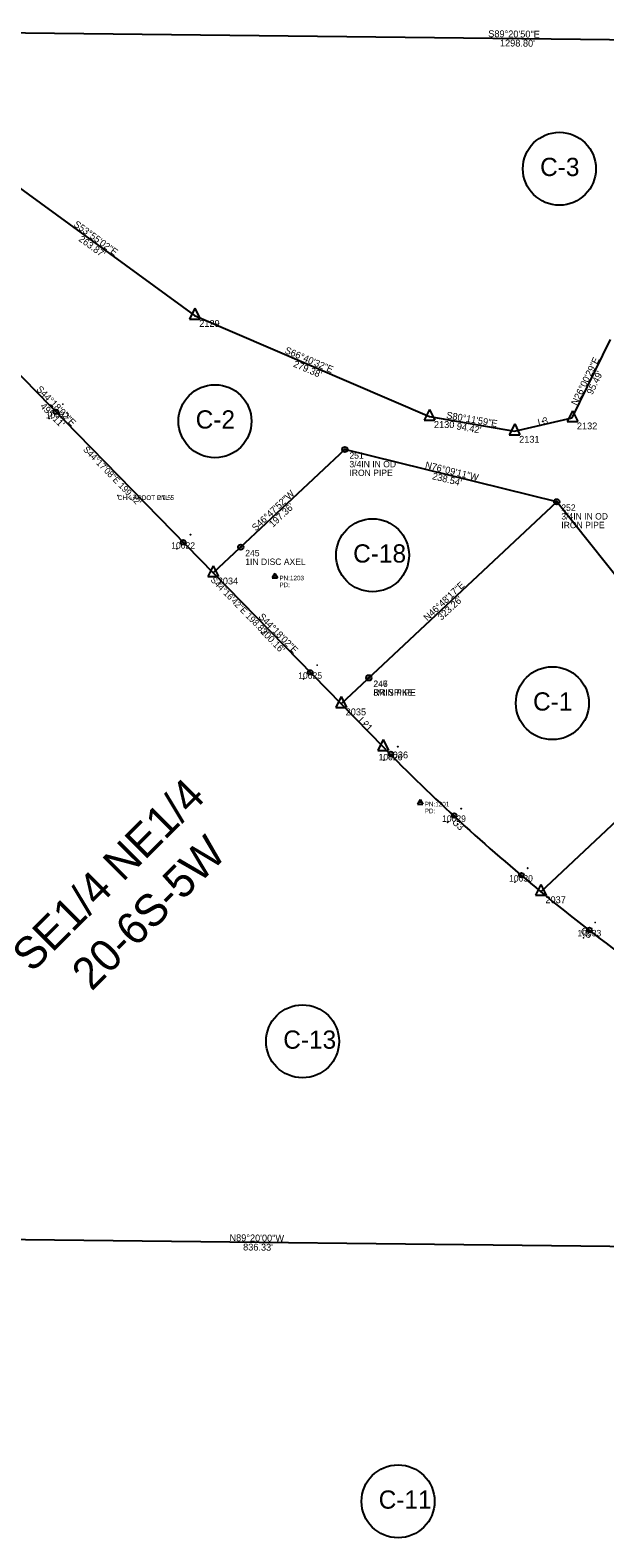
# Model space of a CAD drawing. Extents: x 1431802 to 1457777, y 1852108 to 1876350.
# Drawn here: x 1442574 to 1443202, y 1854628 to 1856278 of the extents above; entities that cross this region are included whole.
import ezdxf

# ---------------------------------------------------------------- set-up
doc = ezdxf.new("R2010")
doc.units = 0
for name, color, linetype in [('Default', 7, 'Continuous'), ('S_CAL_CORNER', 7, 'Continuous'), ('S_CAL_CORNER_ANNOT', 7, 'Continuous'), ('S_EXISTING_ALIGNMENT', 7, 'Continuous'), ('S_EXISTING_ALIGNMENT_ANNOT', 7, 'Continuous'), ('S_IRON_PIN', 7, 'Continuous'), ('S_IRON_PIN_ANNOT', 7, 'Continuous'), ('S_MSC_PT_SYM', 7, 'Continuous'), ('S_PROPERTY', 7, 'Continuous'), ('S_PROPERTY_ANNOT', 7, 'Continuous'), ('S_RDW_PT_SYM', 7, 'Continuous'), ('S_SECONDARY_CTL', 7, 'Continuous'), ('S_SECONDARY_CTL_ANNOT', 7, 'Continuous'), ('S_SECTION_TEXT', 7, 'Continuous'), ('S_SIXTEEN_SECTION', 7, 'Continuous'), ('S_SIXTEEN_SECTION_ANNOT', 7, 'Continuous'), ('S_SURVEY_TEXT_ANNOT', 7, 'Continuous')]:
    doc.layers.add(name, color=color, linetype=linetype)

msp = doc.modelspace()

# ---------------------------------------------------------------- linework, layer by layer
at = {"layer": 'Default'}
for points in [[(1443134.5, 1855849.7), (1443134.5, 1855849.8), (1443134.5, 1855849.7), (1443134.5, 1855849.7), (1443134.5, 1855849.7), (1443134.5, 1855849.7), (1443134.5, 1855849.7), (1443134.6, 1855849.7)], [(1442939.8, 1855519.7), (1442939.9, 1855519.7), (1442939.8, 1855519.7), (1442939.8, 1855519.7), (1442939.8, 1855519.7), (1442939.8, 1855519.6), (1442939.8, 1855519.7), (1442939.9, 1855519.6)], [(1443041.6, 1855409.2), (1443041.7, 1855409.2), (1443041.6, 1855409.2), (1443041.6, 1855409.2), (1443041.6, 1855409.2), (1443041.6, 1855409.2), (1443041.6, 1855409.2), (1443041.7, 1855409.2)], [(1443181.9, 1855290.9), (1443182, 1855290.9), (1443181.9, 1855290.9), (1443181.9, 1855290.9), (1443181.9, 1855290.9), (1443181.9, 1855290.8), (1443181.9, 1855290.9), (1443182, 1855290.8)]]:
    msp.add_lwpolyline(points, dxfattribs=at)
at = {"layer": 'S_CAL_CORNER'}
for p, q in [((1442754.3, 1855973.5), (1442748.4, 1855961.6)), ((1442748.4, 1855961.6), (1442760.1, 1855961.6)), ((1442754.3, 1855973.5), (1442760.1, 1855961.6)), ((1443010.8, 1855862.8), (1443004.9, 1855851)), ((1443010.8, 1855862.8), (1443016.6, 1855851)), ((1443004.9, 1855851), (1443016.6, 1855851)), ((1443103.9, 1855846.8), (1443098, 1855835)), ((1443103.9, 1855846.8), (1443109.7, 1855835)), ((1443167, 1855861.3), (1443161.2, 1855849.5)), ((1443161.2, 1855849.5), (1443172.9, 1855849.5)), ((1443167, 1855861.3), (1443172.9, 1855849.5)), ((1443098, 1855835), (1443109.7, 1855835)), ((1442774.5, 1855691.8), (1442768.6, 1855680)), ((1442774.5, 1855691.8), (1442780.3, 1855680)), ((1442768.6, 1855680), (1442780.3, 1855680)), ((1442914.3, 1855548.6), (1442908.4, 1855536.7)), ((1442908.4, 1855536.7), (1442920.1, 1855536.7)), ((1442914.3, 1855548.6), (1442920.1, 1855536.7)), ((1442960.2, 1855501.5), (1442954.3, 1855489.7)), ((1442960.2, 1855501.5), (1442966, 1855489.7)), ((1442954.3, 1855489.7), (1442966, 1855489.7)), ((1443132.6, 1855343.1), (1443126.7, 1855331.3)), ((1443132.6, 1855343.1), (1443138.4, 1855331.3)), ((1443126.7, 1855331.3), (1443138.4, 1855331.3))]:
    msp.add_line(p, q, dxfattribs=at)
at = {"layer": 'S_EXISTING_ALIGNMENT'}
for centre in [(1442602.6, 1855860.1), (1442741.7, 1855717.4), (1442880.5, 1855575.1), (1442968.6, 1855485.9), (1443037.8, 1855418.6), (1443111.3, 1855353.3), (1443185.6, 1855293.4)]:
    msp.add_circle(centre, 2.5, dxfattribs=at)
at = {"layer": 'S_IRON_PIN'}
for centre, radius in [((1442918.3, 1855818.9), 2.91), ((1442918.3, 1855818.9), 0.411), ((1442918.3, 1855818.9), 0.262), ((1442918.3, 1855818.9), 0.212), ((1442918.3, 1855818.9), 0.145), ((1442918.3, 1855818.9), 0.0581), ((1442918.3, 1855818.9), 0.0822), ((1443149.9, 1855761.8), 2.91), ((1443149.9, 1855761.8), 0.411), ((1443149.9, 1855761.8), 0.262), ((1443149.9, 1855761.8), 0.212), ((1443149.9, 1855761.8), 0.145), ((1443149.9, 1855761.8), 0.0581), ((1443149.9, 1855761.8), 0.0822), ((1442804.5, 1855712.1), 2.91), ((1442804.5, 1855712.1), 0.411), ((1442804.5, 1855712.1), 0.212), ((1442804.5, 1855712.1), 0.262), ((1442804.5, 1855712.1), 0.145), ((1442804.5, 1855712.1), 0.0581), ((1442804.5, 1855712.1), 0.0822), ((1442944.5, 1855569.2), 2.91), ((1442944.5, 1855569), 2.91), ((1442944.5, 1855569.2), 0.411), ((1442944.5, 1855569), 0.411), ((1442944.5, 1855569.2), 0.212), ((1442944.5, 1855569.2), 0.262), ((1442944.5, 1855569), 0.212), ((1442944.5, 1855569), 0.262), ((1442944.5, 1855569.2), 0.145), ((1442944.5, 1855569), 0.145), ((1442944.5, 1855569), 0.0822), ((1442944.5, 1855569.2), 0.0822), ((1442944.5, 1855569.2), 0.0581), ((1442944.5, 1855569), 0.0581)]:
    msp.add_circle(centre, radius, dxfattribs=at)
at = {"layer": 'S_MSC_PT_SYM'}
for points in [[(1442670.3, 1855768.6), (1442670.3, 1855768.7), (1442670.3, 1855768.6), (1442670.3, 1855768.6), (1442670.3, 1855768.6), (1442670.3, 1855768.6), (1442670.3, 1855768.6), (1442670.4, 1855768.6)], [(1442670.3, 1855768.6), (1442670.3, 1855768.7), (1442670.3, 1855768.6), (1442670.3, 1855768.6), (1442670.3, 1855768.6), (1442670.3, 1855768.6), (1442670.3, 1855768.6), (1442670.4, 1855768.6)], [(1442670.3, 1855768.7), (1442670.3, 1855768.7), (1442670.3, 1855768.7), (1442670.3, 1855768.7), (1442670.3, 1855768.7), (1442670.3, 1855768.6), (1442670.3, 1855768.7), (1442670.4, 1855768.7)]]:
    msp.add_lwpolyline(points, dxfattribs=at)
at = {"layer": 'S_PROPERTY'}
for p, q in [((1442540.9, 1856120.9), (1442754.2, 1855965.5)), ((1442428.6, 1856038.2), (1442774.4, 1855683.8)), ((1442754.2, 1855965.5), (1443010.7, 1855854.9)), ((1443166.9, 1855853.4), (1443208.8, 1855939.2)), ((1443010.7, 1855854.9), (1443103.8, 1855838.8)), ((1443103.8, 1855838.8), (1443166.9, 1855853.4)), ((1442918.3, 1855818.9), (1442774.4, 1855683.8)), ((1443149.9, 1855761.8), (1442918.3, 1855818.9)), ((1442914.2, 1855540.6), (1443149.9, 1855761.8)), ((1443336.5, 1855526.9), (1443149.9, 1855761.8)), ((1442774.4, 1855683.8), (1442914.2, 1855540.6)), ((1442914.2, 1855540.6), (1442960.1, 1855493.5)), ((1443132.5, 1855335.1), (1443336.5, 1855526.9)), ((1443244.7, 1854946.5), (1442408.5, 1854956.2))]:
    msp.add_line(p, q, dxfattribs=at)
for centre in [(1443152.8, 1856126), (1442776.4, 1855849.8), (1442948.6, 1855703.2), (1443145.1, 1855541.4), (1442872.1, 1855171.5), (1442976.5, 1854668.3)]:
    msp.add_circle(centre, 39.9, dxfattribs=at)
for start, end in [(224.3006, 230.5345), (230.5345, 234.0557)]:
    msp.add_arc((1444501, 1856997.2), 2153, start, end, dxfattribs=at)
at = {"layer": 'S_RDW_PT_SYM'}
for points in [[(1442610, 1855868.3), (1442610, 1855868.4), (1442610, 1855868.3), (1442610, 1855868.3), (1442610, 1855868.3), (1442610, 1855868.3), (1442610, 1855868.3), (1442610.1, 1855868.3)], [(1442595.2, 1855852.9), (1442595.2, 1855853), (1442595.2, 1855852.9), (1442595.1, 1855852.9), (1442595.2, 1855852.9), (1442595.2, 1855852.9), (1442595.2, 1855852.9), (1442595.2, 1855852.9)], [(1442749.7, 1855725.8), (1442749.7, 1855725.8), (1442749.7, 1855725.8), (1442749.6, 1855725.8), (1442749.7, 1855725.8), (1442749.7, 1855725.7), (1442749.7, 1855725.8), (1442749.7, 1855725.8)], [(1442734.7, 1855710.4), (1442734.7, 1855710.4), (1442734.7, 1855710.4), (1442734.7, 1855710.4), (1442734.7, 1855710.4), (1442734.7, 1855710.3), (1442734.7, 1855710.4), (1442734.8, 1855710.4)], [(1442888.1, 1855582.9), (1442888.1, 1855583), (1442888.1, 1855582.9), (1442888, 1855582.9), (1442888.1, 1855582.9), (1442888.1, 1855582.9), (1442888.1, 1855582.9), (1442888.1, 1855582.9)], [(1442873.3, 1855568.1), (1442873.3, 1855568.2), (1442873.3, 1855568.1), (1442873.3, 1855568.1), (1442873.3, 1855568.1), (1442873.3, 1855568), (1442873.3, 1855568.1), (1442873.4, 1855568.1)], [(1442976.2, 1855493.8), (1442976.2, 1855493.9), (1442976.2, 1855493.8), (1442976.1, 1855493.8), (1442976.2, 1855493.8), (1442976.2, 1855493.8), (1442976.2, 1855493.8), (1442976.2, 1855493.8)], [(1442960.9, 1855479.1), (1442960.9, 1855479.2), (1442960.9, 1855479.1), (1442960.8, 1855479.1), (1442960.9, 1855479.1), (1442960.9, 1855479.1), (1442960.9, 1855479.1), (1442960.9, 1855479.1)], [(1443045.5, 1855426), (1443045.5, 1855426.1), (1443045.5, 1855426), (1443045.5, 1855426), (1443045.5, 1855426), (1443045.5, 1855426), (1443045.5, 1855426), (1443045.6, 1855426)], [(1443030.7, 1855411.2), (1443030.7, 1855411.3), (1443030.7, 1855411.2), (1443030.6, 1855411.2), (1443030.7, 1855411.2), (1443030.7, 1855411.2), (1443030.7, 1855411.2), (1443030.7, 1855411.2)], [(1443118.2, 1855361.1), (1443118.2, 1855361.1), (1443118.2, 1855361.1), (1443118.1, 1855361.1), (1443118.2, 1855361.1), (1443118.2, 1855361), (1443118.2, 1855361.1), (1443118.2, 1855361.1)], [(1443104, 1855345.5), (1443104, 1855345.6), (1443104, 1855345.5), (1443103.9, 1855345.5), (1443104, 1855345.5), (1443104, 1855345.5), (1443104, 1855345.5), (1443104, 1855345.5)], [(1443192, 1855301.4), (1443192, 1855301.5), (1443192, 1855301.4), (1443191.9, 1855301.4), (1443192, 1855301.4), (1443192, 1855301.4), (1443192, 1855301.4), (1443192, 1855301.4)], [(1443179, 1855284.7), (1443179, 1855284.8), (1443179, 1855284.7), (1443179, 1855284.7), (1443179, 1855284.7), (1443179, 1855284.7), (1443179, 1855284.7), (1443179.1, 1855284.7)]]:
    msp.add_lwpolyline(points, dxfattribs=at)
at = {"layer": 'S_SECONDARY_CTL'}
for p, q in [((1442841.8, 1855683.4), (1442838.8, 1855678.4)), ((1442841.8, 1855683.4), (1442844.7, 1855678.4)), ((1442838.8, 1855678.4), (1442844.7, 1855678.4)), ((1443000.6, 1855436.1), (1442997.6, 1855431.1)), ((1443000.6, 1855436.1), (1443003.5, 1855431.1)), ((1442997.6, 1855431.1), (1443003.5, 1855431.1))]:
    msp.add_line(p, q, dxfattribs=at)
for centre, radius in [((1442841.8, 1855680.8), 0.311), ((1442841.8, 1855680.8), 0.183), ((1442841.8, 1855680.8), 0.103), ((1443000.6, 1855433.5), 0.311), ((1443000.6, 1855433.5), 0.183), ((1443000.6, 1855433.5), 0.103)]:
    msp.add_circle(centre, radius, dxfattribs=at)
at = {"layer": 'S_SIXTEEN_SECTION'}
msp.add_line((1442459.3, 1856275.8), (1443758, 1856261), dxfattribs=at)

# ---------------------------------------------------------------- texts
at = {"layer": 'S_CAL_CORNER_ANNOT'}
for s, p in [('2129', (1442759.2, 1855953)), ('2130', (1443015.7, 1855842.4)), ('2132', (1443171.9, 1855840.9)), ('2131', (1443108.8, 1855826.3)), ('2034', (1442779.4, 1855671.3)), ('2035', (1442919.2, 1855528.1)), ('2036', (1442965.1, 1855481)), ('2037', (1443137.5, 1855322.6))]:
    msp.add_text(s, height=7.5, dxfattribs=at).set_placement(p)
at = {"layer": 'S_EXISTING_ALIGNMENT_ANNOT'}
for s, p in [('10021', (1442591.4, 1855853.1)), ('10022', (1442728.6, 1855710.4)), ('10025', (1442867.4, 1855568.1)), ('10026', (1442955.2, 1855478.9)), ('10029', (1443024.6, 1855411.6)), ('10030', (1443097.8, 1855346.3)), ('10033', (1443172.5, 1855286.4))]:
    msp.add_text(s, height=7, dxfattribs=at).set_placement(p)
for s, rotation, p in [('S44%%d17\'08"E 199.32\'', 314.2855, (1442631.8, 1855818.3)), ('S44%%d16\'42"E 198.83\'', 314.2783, (1442770.9, 1855675.7))]:
    msp.add_text(s, height=7, rotation=rotation, dxfattribs=at).set_placement(p)
at = {"layer": 'S_IRON_PIN_ANNOT'}
for s, p in [('251', (1442923.3, 1855808.9)), ('3/4IN IN OD', (1442923.3, 1855799.4)), ('IRON PIPE', (1442923.3, 1855789.9)), ('3/4IN IN OD', (1443154.9, 1855742.3)), ('252', (1443154.9, 1855751.8)), ('IRON PIPE', (1443154.9, 1855732.8)), ('245', (1442809.5, 1855702.1)), ('1IN DISC AXEL', (1442809.5, 1855692.6)), ('246', (1442949.5, 1855559.2)), ('247', (1442949.5, 1855559)), ('3/4IN PIPE', (1442949.5, 1855549.5)), ('RR SPIKE', (1442949.5, 1855549.7))]:
    msp.add_text(s, height=7, dxfattribs=at).set_placement(p)
at = {"layer": 'S_PROPERTY'}
for s, p in [('C-3', (1443131.7, 1856118)), ('C-2', (1442755.3, 1855841.8)), ('C-18', (1442927.4, 1855695.2)), ('C-1', (1443124, 1855533.3)), ('C-13', (1442851, 1855163.4)), ('C-11', (1442955.3, 1854660.3))]:
    msp.add_text(s, height=19.95, dxfattribs=at).set_placement(p)
at = {"layer": 'S_PROPERTY_ANNOT'}
for s, rotation, p in [('S53%%d55\'02"E', 323.9171, (1442621.3, 1856063.8)), ("263.87'", 323.9171, (1442626.7, 1856047.6)), ('S66%%d40\'32"E', 336.6754, (1442852, 1855924.7)), ("279.38'", 336.6754, (1442861.3, 1855909.8)), ('N26%%d00\'29"E', 63.992, (1443171.9, 1855866.4)), ("95.49'", 63.992, (1443188.8, 1855878.2)), ('S44%%d18\'02"E', 314.3006, (1442580.6, 1855884.2)), ("495.11'", 314.3006, (1442584.8, 1855865.6)), ('S80%%d11\'59"E', 350.1997, (1443028.8, 1855853)), ("94.42'", 350.1997, (1443040.1, 1855840.9)), ('L3', 12.9921, (1443130, 1855844.8)), ('N76%%d09\'11"W', 346.1529, (1443005.5, 1855798.7)), ("238.54'", 346.1529, (1443013.3, 1855786.5)), ('S46%%d47\'52"W', 43.2024, (1442820.9, 1855729.2)), ("197.36'", 43.2024, (1442839.7, 1855733.2)), ('N46%%d48\'17"E', 43.1951, (1443008.5, 1855630.8)), ("323.26'", 43.1951, (1443023.9, 1855631.5)), ('S44%%d18\'02"E', 314.3006, (1442823.4, 1855635.4)), ("200.16'", 314.3006, (1442825.5, 1855618.9)), ('L21', 314.3006, (1442932.5, 1855521.9)), ('C3', 317.4175, (1443034.9, 1855410.3)), ('C5', 322.2951, (1443175.1, 1855291.4)), ('N89%%d20\'00"W', 359.3333, (1442792.2, 1854953)), ("836.33'", 359.3333, (1442807.1, 1854942.8))]:
    msp.add_text(s, height=7.5, rotation=rotation, dxfattribs=at).set_placement(p)
at = {"layer": 'S_SECONDARY_CTL'}
for p in [(1442840.6, 1855678.7), (1442999.4, 1855431.5)]:
    msp.add_text('TV', height=1.5, dxfattribs=at).set_placement(p)
at = {"layer": 'S_SECONDARY_CTL_ANNOT'}
for s, p in [('PN:1203', (1442846.8, 1855675.8)), ('PD:', (1442846.8, 1855668.3)), ('PN:1201', (1443005.6, 1855428.5)), ('PD:', (1443005.6, 1855421))]:
    msp.add_text(s, height=5, dxfattribs=at).set_placement(p)
at = {"layer": 'S_SECTION_TEXT'}
for s, p in [('SE1/4 NE1/4', (1442576.4, 1855245.8)), ('20-6S-5W', (1442641.5, 1855225.6))]:
    msp.add_text(s, height=35, rotation=45, dxfattribs=at).set_placement(p)
at = {"layer": 'S_SIXTEEN_SECTION_ANNOT'}
for s, p in [('S89%%d20\'50"E', (1443075, 1856270)), ("1298.80'", (1443087.8, 1856259.9))]:
    msp.add_text(s, height=7.5, rotation=359.3472, dxfattribs=at).set_placement(p)
at = {"layer": 'S_SURVEY_TEXT_ANNOT'}
for s, p in [('CHK ARDOT PN 5', (1442670.3, 1855763.6)), ('CHK ARDOT PN 5', (1442670.3, 1855763.6)), ('CHK ARDOT CTL 5', (1442670.3, 1855763.7))]:
    msp.add_text(s, height=5, dxfattribs=at).set_placement(p)

doc.saveas('drawing.dxf')
